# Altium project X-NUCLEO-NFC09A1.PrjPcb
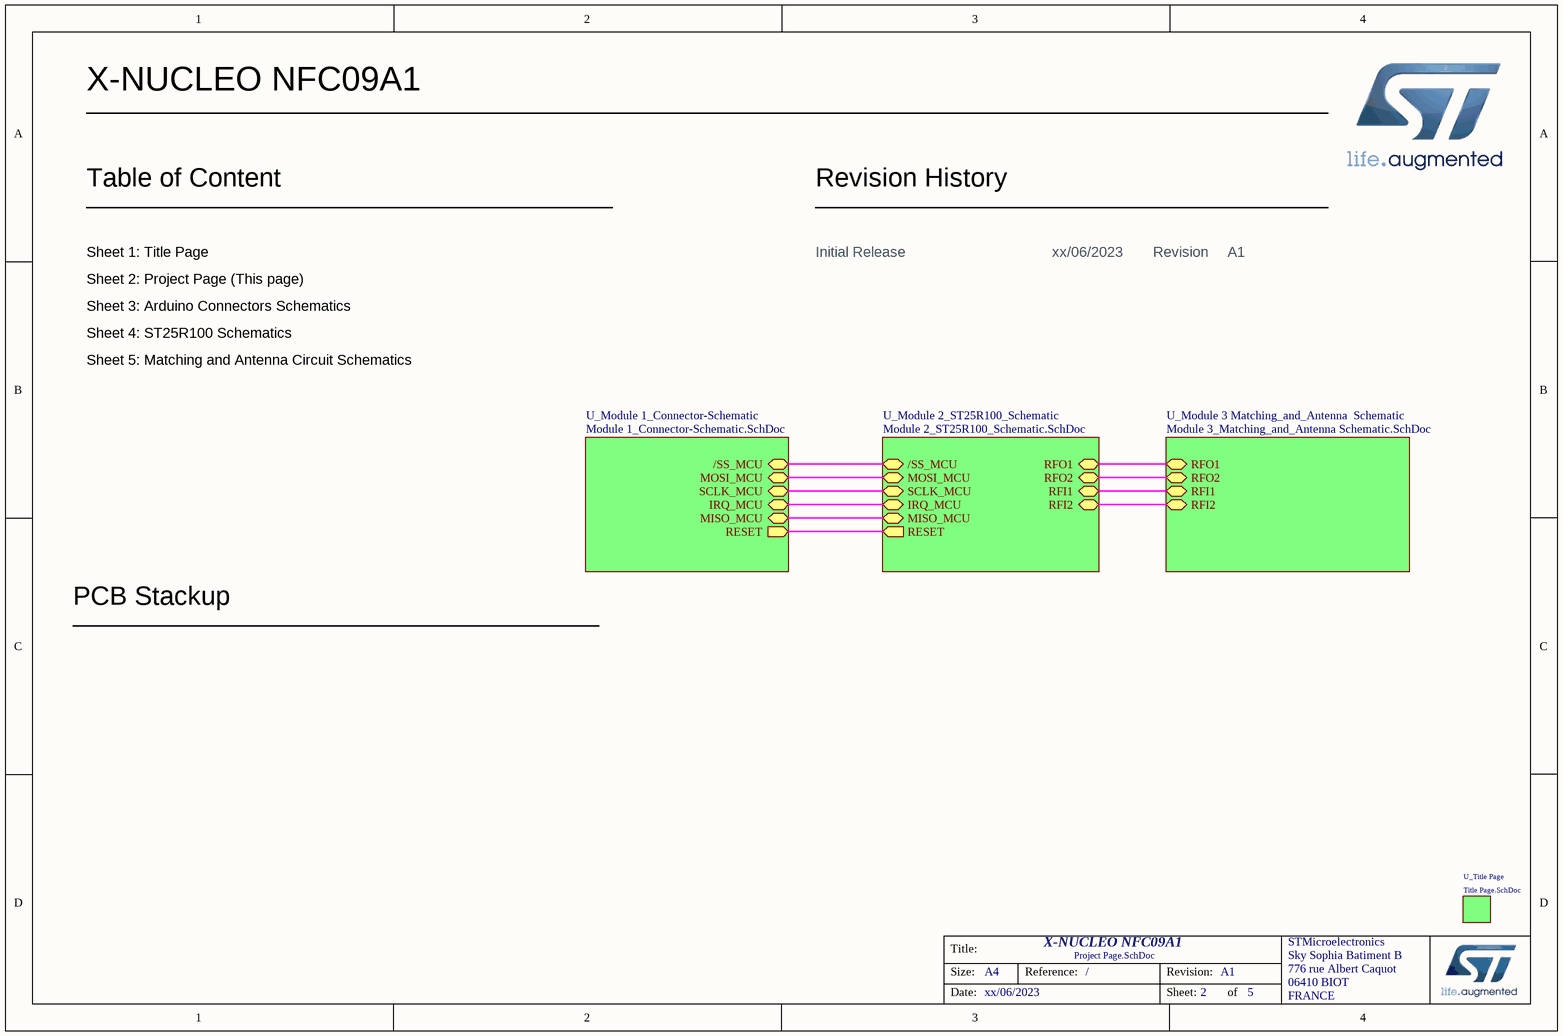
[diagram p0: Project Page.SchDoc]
Company: ST MICROELECTRONICS; date_Dossier: xx/06/2023; Reference: /; Revision: A1; Schematics_Reference: /; Schematics_Revision: A1; Schematics_Title: X-NUCLEO NFC09A1; text_ident_couches: X-NUCLEO NFC09A1; Title: X-NUCLEO NFC09A1; Titre_BOM: X-NUCLEO NFC09A1
5 sheets, 123 parts. Net scope: hierarchical (ports join the sheet entries above them; power ports are global).
Board file: X-NUCLEO-NFC09A1.PcbDoc
Sheets:
  Project Page.SchDoc
    U_Module 1_Connector-Schematic = Module 1_Connector-Schematic.SchDoc
    U_Module 3 Matching_and_Antenna  Schematic = Module 3_Matching_and_Antenna Schematic.SchDoc
    U_Module 2_ST25R100_Schematic = Module 2_ST25R100_Schematic.SchDoc
    U_Title Page = Title Page.SchDoc

## Sheet Project Page.SchDoc: X-NUCLEO NFC09A1
size A4; PageSetup: Record=PageOptions¦CenterHorizontal=True¦CenterVertical=True¦PrintScale=1.00¦XCorrection=1.00¦YCorrection=1.00¦PrintKind=0¦BorderSize=5000000¦LeftOffset=0¦BottomOffset=0¦Orientation=2¦PaperLength=1000¦PaperWidth=1000¦Scale=100¦PaperSource=7¦PrintQuality=-4¦MediaType=1¦DitherType=10¦PrintScaleMode=1¦PaperKind=A4; Revision: A1; SheetNumber: 2; SheetTotal: 5; Reference: /

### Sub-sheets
U_Module 1_Connector-Schematic = Module 1_Connector-Schematic.SchDoc: /SS_MCU (bidir), MOSI_MCU (bidir), SCLK_MCU (bidir), IRQ_MCU (bidir), MISO_MCU (bidir), RESET (out)
U_Module 2_ST25R100_Schematic = Module 2_ST25R100_Schematic.SchDoc: RFO1 (bidir), RFO2 (bidir), RFI1 (bidir), RFI2 (bidir), /SS_MCU (bidir), MOSI_MCU (bidir), SCLK_MCU (bidir), IRQ_MCU (bidir), MISO_MCU (bidir), RESET (out)
U_Module 3 Matching_and_Antenna  Schematic = Module 3_Matching_and_Antenna Schematic.SchDoc: RFO1 (bidir), RFO2 (bidir), RFI1 (bidir), RFI2 (bidir)
U_Title Page = Title Page.SchDoc: no entries

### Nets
/SS_MCU: sheet U_Module 1_Connector-Schematic//SS_MCU, sheet U_Module 2_ST25R100_Schematic//SS_MCU
IRQ_MCU: sheet U_Module 1_Connector-Schematic/IRQ_MCU, sheet U_Module 2_ST25R100_Schematic/IRQ_MCU
MISO_MCU: sheet U_Module 1_Connector-Schematic/MISO_MCU, sheet U_Module 2_ST25R100_Schematic/MISO_MCU
MOSI_MCU: sheet U_Module 1_Connector-Schematic/MOSI_MCU, sheet U_Module 2_ST25R100_Schematic/MOSI_MCU
RESET: sheet U_Module 1_Connector-Schematic/RESET, sheet U_Module 2_ST25R100_Schematic/RESET
RFI1: sheet U_Module 3 Matching_and_Antenna  Schematic/RFI1, sheet U_Module 2_ST25R100_Schematic/RFI1
RFI2: sheet U_Module 3 Matching_and_Antenna  Schematic/RFI2, sheet U_Module 2_ST25R100_Schematic/RFI2
RFO1: sheet U_Module 3 Matching_and_Antenna  Schematic/RFO1, sheet U_Module 2_ST25R100_Schematic/RFO1
RFO2: sheet U_Module 3 Matching_and_Antenna  Schematic/RFO2, sheet U_Module 2_ST25R100_Schematic/RFO2
SCLK_MCU: sheet U_Module 1_Connector-Schematic/SCLK_MCU, sheet U_Module 2_ST25R100_Schematic/SCLK_MCU

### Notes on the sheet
- Table of Content
- Revision History
- Sheet 1: Title Page
- Sheet 2: Project Page (This page)
- Sheet 3: Arduino Connectors Schematics
- Initial Release
- Revision
- A1
- Sheet 4: ST25R100 Schematics
- Sheet 5: Matching and Antenna Circuit Schematics
- PCB Stackup

## Sheet Module 1_Connector-Schematic.SchDoc: X-NUCLEO NFC09A1
size A4; PageSetup: Record=PageOptions¦CenterHorizontal=True¦CenterVertical=True¦PrintScale=0.73¦XCorrection=1.00¦YCorrection=1.00¦PrintKind=0¦BorderSize=5000000¦LeftOffset=0¦BottomOffset=0¦Orientation=2¦PaperLength=1000¦PaperWidth=1000¦Scale=100¦PaperSource=7¦PrintQuality=-3¦MediaType=1¦DitherType=10¦PrintScaleMode=1¦PaperKind=A4¦PaperIndex=9; Revision: A1; SheetNumber: 3; SheetTotal: 5; Reference: /
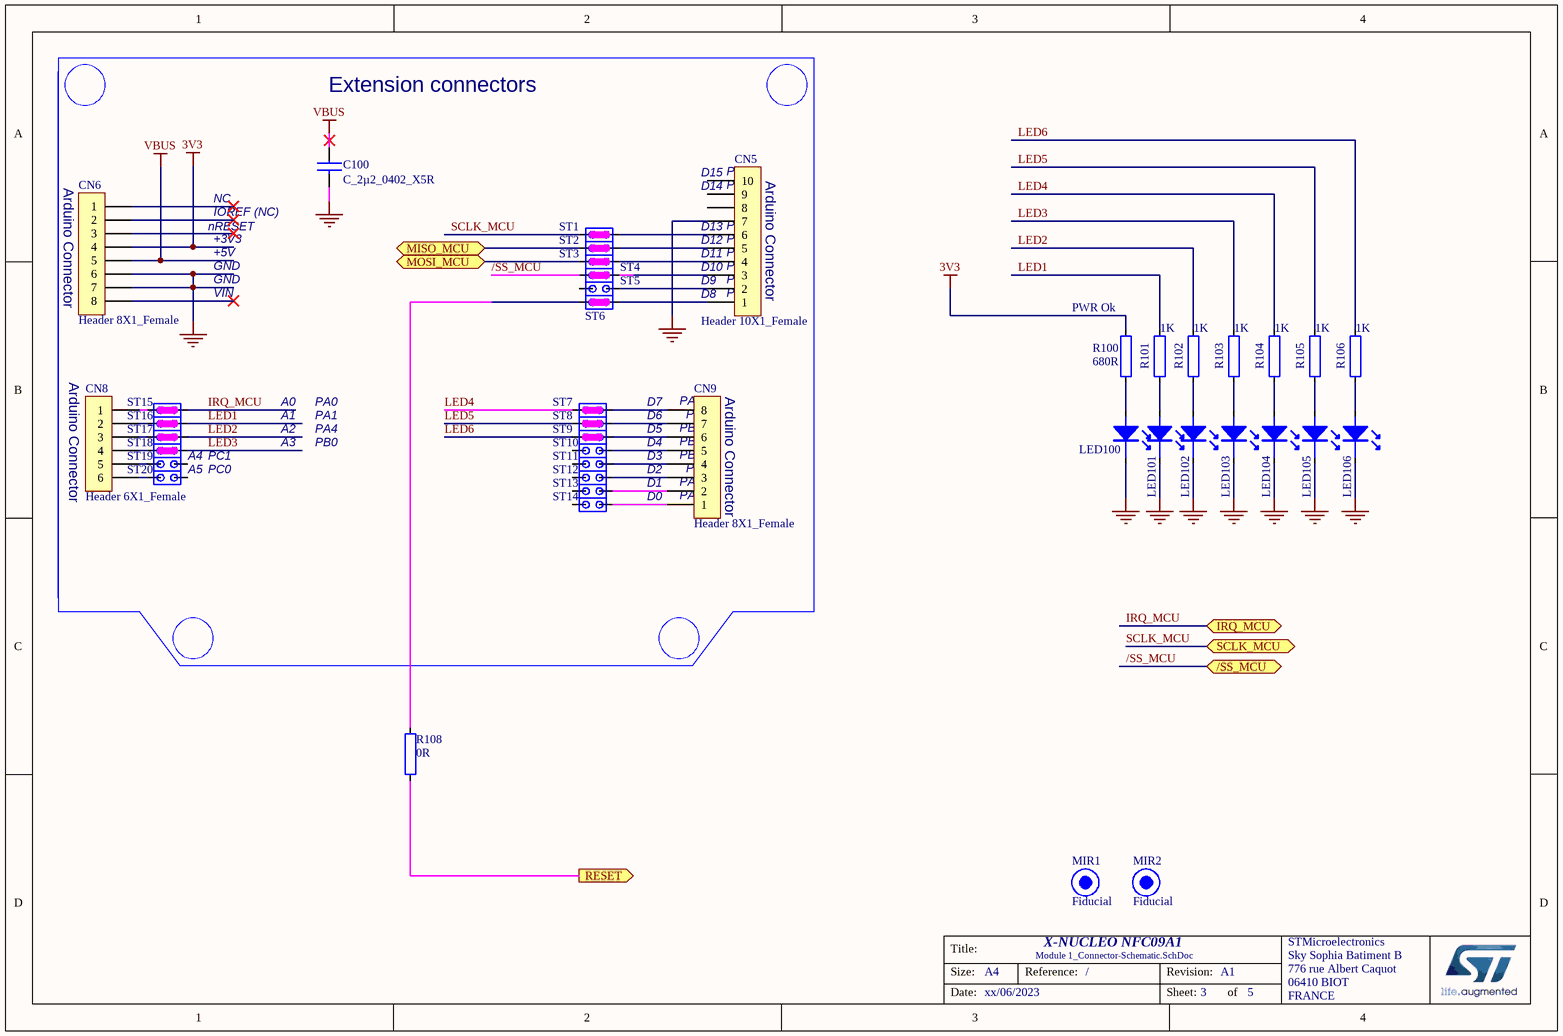
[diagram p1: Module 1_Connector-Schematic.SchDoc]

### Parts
C100  C_2µ2_0402_X5R  [C0402]
CN5  Header 10X1_Female  [SAMTEC-SSQ-1x10-DROIT-STYLE-03]
CN6  Header 8X1_Female  [SAMTEC-SSQ-1x8-DROIT-STYLE-03]
CN8  Header 6X1_Female  [SAMTEC-SSQ-1x6-DROIT-STYLE-03]
CN9  Header 8X1_Female  [SAMTEC-SSQ-1x8-DROIT-STYLE-03]
LED100  Green  [D0603]  (value not drawn)
LED101  Blue  [D0603]  (value not drawn)
LED102  Blue  [D0603]  (value not drawn)
LED103  Blue  [D0603]  (value not drawn)
LED104  Blue  [D0603]  (value not drawn)
LED105  Blue  [D0603]  (value not drawn)
LED106  Blue  [D0603]  (value not drawn)
MIR1  Fiducial  [mire_optique_standard]  (no BOM)
MIR2  Fiducial  [mire_optique_standard]  (no BOM)
R100  680R  [R0402]
R101  1K  [R0402]
R102  1K  [R0402]
R103  1K  [R0402]
R104  1K  [R0402]
R105  1K  [R0402]
R106  1K  [R0402]
R108  0R  [R0402]
ST1  HE14 2PTS NC  [HE14-1x2-DROIT-AVEC-STRAP-CUIVRE-BOTTOM]  (value not drawn)  (net tie)
ST2  HE14 2PTS NC  [HE14-1x2-DROIT-AVEC-STRAP-CUIVRE-BOTTOM]  (value not drawn)  (net tie)
ST3  HE14 2PTS NC  [HE14-1x2-DROIT-AVEC-STRAP-CUIVRE-BOTTOM]  (value not drawn)  (net tie)
ST4  HE14 2PTS NC  [HE14-1x2-DROIT-AVEC-STRAP-CUIVRE-BOTTOM]  (value not drawn)  (net tie)
ST5  HE14 2PTS NC  [HE14-1x2-DROIT]  (value not drawn)
ST6  HE14 2PTS NC  [HE14-1x2-DROIT-AVEC-STRAP-CUIVRE-BOTTOM]  (value not drawn)  (net tie)
ST7  HE14 2PTS NC  [HE14-1x2-DROIT-AVEC-STRAP-CUIVRE-BOTTOM]  (value not drawn)  (net tie)
ST8  HE14 2PTS NC  [HE14-1x2-DROIT-AVEC-STRAP-CUIVRE-BOTTOM]  (value not drawn)  (net tie)
ST9  HE14 2PTS NC  [HE14-1x2-DROIT-AVEC-STRAP-CUIVRE-BOTTOM]  (value not drawn)  (net tie)
ST10  HE14 2PTS NC  [HE14-1x2-DROIT]  (value not drawn)
ST11  HE14 2PTS NC  [HE14-1x2-DROIT]  (value not drawn)
ST12  HE14 2PTS NC  [HE14-1x2-DROIT]  (value not drawn)
ST13  HE14 2PTS NC  [HE14-1x2-DROIT]  (value not drawn)
ST14  HE14 2PTS NC  [HE14-1x2-DROIT]  (value not drawn)
ST15  HE14 2PTS NC  [HE14-1x2-DROIT-AVEC-STRAP-CUIVRE-BOTTOM]  (value not drawn)  (net tie)
ST16  HE14 2PTS NC  [HE14-1x2-DROIT-AVEC-STRAP-CUIVRE-BOTTOM]  (value not drawn)  (net tie)
ST17  HE14 2PTS NC  [HE14-1x2-DROIT-AVEC-STRAP-CUIVRE-BOTTOM]  (value not drawn)  (net tie)
ST18  HE14 2PTS NC  [HE14-1x2-DROIT-AVEC-STRAP-CUIVRE-BOTTOM]  (value not drawn)  (net tie)
ST19  HE14 2PTS NC  [HE14-1x2-DROIT-SANS-3D]  (value not drawn)
ST20  HE14 2PTS NC  [HE14-1x2-DROIT-SANS-3D]  (value not drawn)

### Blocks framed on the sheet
Extension connectors: C100 CN5 CN6 CN8 CN9 ST1-ST20

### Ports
/SS_MCU (bidir), IRQ_MCU (bidir), MISO_MCU (bidir), MOSI_MCU (bidir), RESET (out), SCLK_MCU (bidir)

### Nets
3V3: CN6.4 R100.2
GND: C100.2 CN5.7 CN6.6 CN6.7 LED100.2 LED101.2 LED102.2 LED103.2 LED104.2 LED105.2 LED106.2
VBUS: C100.1 CN6.5  [project net V_RF]
/SS_MCU: ST4.1 ; port /SS_MCU
IRQ_MCU: ST15.2 ; port IRQ_MCU
LED1: R101.2 ST16.2
LED2: R102.2 ST17.2
LED3: R103.2 ST18.2
LED4: R104.2 ST7.1
LED5: R105.2 ST8.1
LED6: R106.2 ST9.1
MISO_MCU: ST2.1 ; port MISO_MCU
MOSI_MCU: ST3.1 ; port MOSI_MCU
RESET: R108.1 ; port RESET
SCLK_MCU: ST1.1 ; port SCLK_MCU
NetCN5_1: CN5.1 ST6.2
NetCN5_2: CN5.2 ST5.2
NetCN5_3: CN5.3 ST4.2
NetCN5_4: CN5.4 ST3.2
NetCN5_5: CN5.5 ST2.2
NetCN5_6: CN5.6 ST1.2
NetCN8_1: CN8.1 ST15.1
NetCN8_2: CN8.2 ST16.1
NetCN8_3: CN8.3 ST17.1
NetCN8_4: CN8.4 ST18.1
NetCN8_5: CN8.5 ST19.1
NetCN8_6: CN8.6 ST20.1
NetCN9_1: CN9.1 ST14.2
NetCN9_2: CN9.2 ST13.2
NetCN9_3: CN9.3 ST12.2
NetCN9_4: CN9.4 ST11.2
NetCN9_5: CN9.5 ST10.2
NetCN9_6: CN9.6 ST9.2
NetCN9_7: CN9.7 ST8.2
NetCN9_8: CN9.8 ST7.2
NetLED100_1: LED100.1 R100.1
NetLED101_1: LED101.1 R101.1
NetLED102_1: LED102.1 R102.1
NetLED103_1: LED103.1 R103.1
NetLED104_1: LED104.1 R104.1
NetLED105_1: LED105.1 R105.1
NetLED106_1: LED106.1 R106.1
NetR108_2: R108.2 ST6.1

Not connected (* = marked no-connect by the designer): CN5 8 9 10; CN6 1* 2* 3* 8*; ST5 1; ST10 1; ST11 1; ST12 1; ST13 1; ST14 1; ST19 2; ST20 2

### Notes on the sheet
- (near CN5) D15
- (near CN5) PB8
- (near CN5) Arduino Connector
- (near CN6) Arduino Connector
- nRESET
- NC
- IOREF (NC)
- +3V3
- (near CN5) D14
- (near CN5) D13
- (near CN5) D12
- (near CN5) PB9
- (near CN5) PA5
- (near CN5) PA6
- +5V
- GND
- VIN
- (near CN5) D8
- (near CN5) D9
- (near CN5) D10
- (near CN5) D11
- (near CN5) PA7
- (near CN5) PB6
- (near CN5) PC7
- (near CN5) PA9
- (near R100) PWR Ok
- (near CN8) Arduino Connector
- A0
- A1
- A2
- A3
- PA0
- PA1
- PA4
- PB0
- D4
- D5
- D6
- D7
- (near CN9) PA8
- (near CN9) PB4
- (near CN9) PB5
- (near CN9) PB10
- (near CN9) Arduino Connector
- A4
- A5
- PC1
- PC0
- D0
- D1
- D2
- D3
- (near CN9) PB3
- (near CN9) PA2
- (near CN9) PA3
- (near CN9) PA10

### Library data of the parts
C100 = C_2µ2_0402_X5R: 2u2_X5R; Manufacturer: MURATA; Manufacturer Part Number: GRM155R60J225ME15D; 2nd Source: 0402, 2.2 µF, 6.3 V, ± 20%, X5R; PickPlace: Yes
CN5 = Header 10X1_Female: Header, 10-Pin, Single row,female; Manufacturer: Samtec; Manufacturer Part Number: SSQ-110-03-L-S; Comments: RECEPTACLE, 2.54MM, SINGLE ROW, 10WAY; 2nd source: doublesourcing allowed; PickPlace: No
CN6 CN9 = Header 8X1_Female: Header, 8-Pin, Single row,female; Manufacturer: Samtec; Manufacturer Part Number: SSQ-108-03-L-S; Comments: RECEPTACLE, 2.54MM, SINGLE ROW, 8WAY; 2nd source: doublesourcing allowed; PickPlace: No
CN8 = Header 6X1_Female: Header, 6-Pin, Single row,female; Manufacturer: Samtec; Manufacturer Part Number: SSQ-106-03-L-S; Comments: RECEPTACLE, 2.54MM, SINGLE ROW, 6 WAY; 2nd source: doublesourcing allowed; PickPlace: No
LED100 = LED-0603-Green: Manufacturer: Lite-On; Manufacturer Part Number: LTST-C190KGKT; PickPlace: Yes
LED101-LED106 = LED-0603-Blue: Manufacturer: Lite-On; Manufacturer Part Number: LTST-C190TBKT; PickPlace: Yes
MIR1 MIR2 = Mire-Optique: Fiducial for SMD Components; PickPlace: Yes
R100 = R0402_680R: 680R, 0402; Manufacturer: Yageo; Manufacturer Part Number: RC0402JR-07680RL; 2nd Source: 680 Ohm ±5% 0.063W, 1/16W Chip Resistor 0402; PickPlace: Yes
R101-R106 = R0402_1k: 1k, 0402; Manufacturer: Panasonic; Manufacturer Part Number: ERJ2GEJ102X; 2nd Source: 1 kohm, 50 V, 0402, >100 mW, ± 5%; PickPlace: Yes
R108 = R0402_0R: 0R, 0402; Manufacturer: MULTI-SOURCES; Manufacturer Part Number: RESISTOR 0402 0R 62mW; 2nd Source: 0 ohm, 50 V, 0402, >62.5 mW; PickPlace: Yes
ST1-ST4 ST7-ST9 ST15-ST18 = HE14-1X2-MALE-DROIT-NC-STRAP-CUIVRE-BOTTOM: CONN HE14 2PTS MALE VERTICAL NOT FITTED; 2nd Source: doublesourcing allowed; PickPlace: No
ST5 ST10-ST14 = HE14-1X2-MALE-DROIT-NC: CONN HE14 2PTS MALE VERTICAL NOT FITTED; 2nd Source: doublesourcing allowed; PickPlace: No
ST6 = HE14-1X2-MALE-DROIT-NC-STRAP-CUIVRE-BOTTOM: CONN HE14 2PTS MALE VERTICAL NOT FITTED; Manufacturer: MULTI SOURCES; 2nd Source: doublesourcing allowed; PickPlace: No
ST19 ST20 = HE14-1X2-MALE-DROIT-NC: CONN HE14 2PTS MALE VERTICAL NOT FITTED; Manufacturer: MULTI-SOURCES; 2nd Source: doublesourcing allowed; PickPlace: No

## Sheet Module 3_Matching_and_Antenna Schematic.SchDoc: X-NUCLEO NFC09A1
size A4; PageSetup: Record=PageOptions¦CenterHorizontal=True¦CenterVertical=True¦PrintScale=0.97¦XCorrection=1.00¦YCorrection=1.00¦PrintKind=0¦BorderSize=5000000¦LeftOffset=0¦BottomOffset=0¦Orientation=2¦PaperLength=1000¦PaperWidth=1000¦Scale=100¦PaperSource=7¦PrintQuality=-4¦MediaType=1¦DitherType=10¦PaperKind=A4¦PrintScaleMode=1; Revision: A1; SheetNumber: 5; SheetTotal: 5; Reference: /
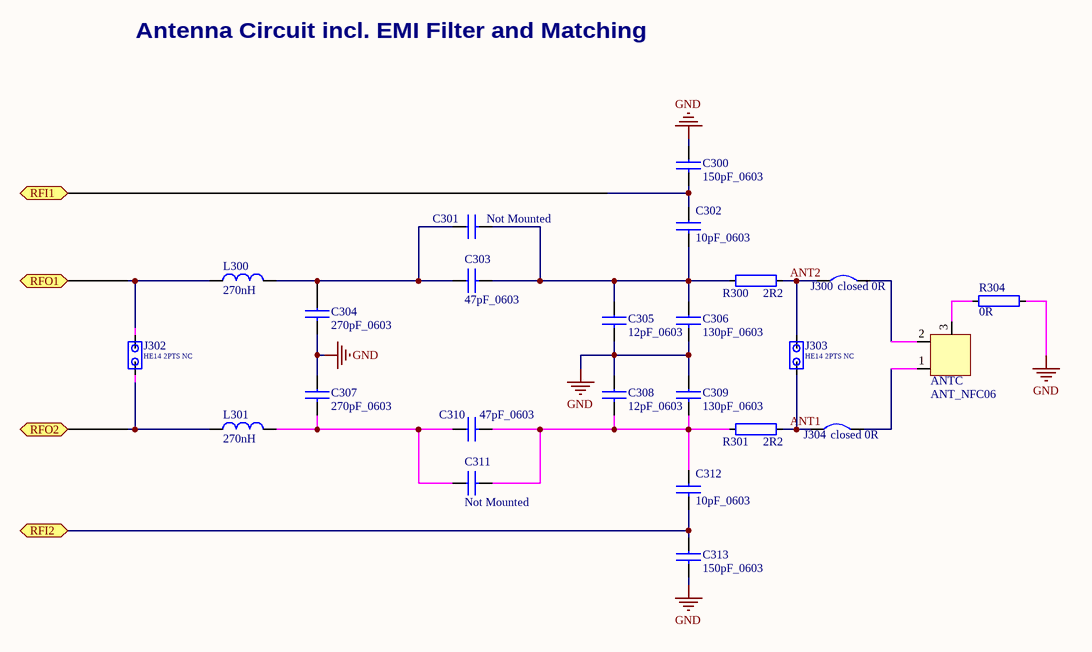
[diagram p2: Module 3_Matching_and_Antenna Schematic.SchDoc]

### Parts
ANTC  ANT_NFC06  [ANT_NFC08]  (net tie, no BOM)
C300  150pF_0603  [C0603]
C301  Not Mounted  [C0603]
C302  10pF_0603  [C0603]
C303  47pF_0603  [C0603]
C304  270pF_0603  [C0603]
C305  12pF_0603  [C0603]
C306  130pF_0603  [C0603]
C307  270pF_0603  [C0603]
C308  12pF_0603  [C0603]
C309  130pF_0603  [C0603]
C310  47pF_0603  [C0603]
C311  Not Mounted  [C0603]
C312  10pF_0603  [C0603]
C313  150pF_0603  [C0603]
J300  closed 0R  [JP2_SMD_closed_0402]  (net tie)
J302  HE14 2PTS NC  [HE14-1x2-DROIT-sans-3D-largeur-1.8]
J303  HE14 2PTS NC  [HE14-1x2-DROIT-sans-3D-largeur-1.8]
J304  closed 0R  [JP2_SMD_closed_0402]  (net tie)
L300  270nH  [L0603]
L301  270nH  [L0603]
R300  2R2  [R0603]
R301  2R2  [R0603]
R304  0R  [R0603]

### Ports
RFI1 (bidir), RFI2 (bidir), RFO1 (bidir), RFO2 (bidir)

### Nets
GND: C300.1 C304.2 C305.2 C306.2 C307.1 C308.1 C309.1 C313.2 R304.1
ANT1: J303.2 J304.1 R301.1
ANT2: J300.1 J303.1 R300.1
RFI1: C300.2 C302.1 ; port RFI1
RFI2: C312.2 C313.1 ; port RFI2
RFO1: J302.1 L300.2 ; port RFO1
RFO2: J302.2 L301.2 ; port RFO2
NetANTC_1: ANTC.1 J304.2
NetANTC_2: ANTC.2 J300.2
NetANTC_3: ANTC.3 R304.2
NetC301_1: C301.1 C303.1 C304.1 L300.1
NetC301_2: C301.2 C302.2 C303.2 C305.1 C306.1 R300.2
NetC307_2: C307.2 C310.1 C311.1 L301.1
NetC308_2: C308.2 C309.2 C310.2 C311.2 C312.1 R301.2

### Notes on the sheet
- Antenna Circuit incl. EMI Filter and Matching

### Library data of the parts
ANTC = ANT_NFC06: PickPlace: No
C300 C313 = C_150p_0603: 150p_COG 0603; Manufacturer: MURATA; Manufacturer Part Number: GRM1885C1H151GA01D; PickPlace: Yes
C301 C311 = C_12p_0603: Manufacturer: MULTI-SOURCES; PickPlace: Yes
C302 C312 = C_10p_0603: 10p_COG; Manufacturer: MULTICOMP; Manufacturer Part Number: MC0603N100F500CT; PickPlace: Yes
C303 = C_82p_0603: 47p_COG; Manufacturer: MURATA; Manufacturer Part Number: GCM1555C1H47FA16D; 2nd Source: 82pF ±1% 50V  C0G, NP0 0603; PickPlace: Yes
C304 C307 = C_680p_0603: 270p_COG; Manufacturer: MURATA; Manufacturer Part Number: GCM1555C1H271FA01D; 2nd Source: 270pF ±2% 50V  C0G, NP0 0603; PickPlace: Yes
C305 C308 = C_5p6_0603: 12pF_COG 0603; Manufacturer: MURATA; Manufacturer Part Number: GRM1555C1H120GA01D; PickPlace: Yes
C306 C309 = C_120p_0603: 130pF_COG; Manufacturer: MURATA; Manufacturer Part Number: GCM1555C1H131FA16D; 2nd Source: 130pF ±1% 50V  C0G, NP0 0603; PickPlace: Yes
C310 = C_82p_0603: 47p_COG; Manufacturer: MURATA; Manufacturer Part Number: GCM1555C1H47FA16D; 2nd Source: 47pF ±1% 50V  C0G, NP0 0603; PickPlace: Yes
J300 J304 = solder_jumper_closed_0402: 0R 0402; Manufacturer: MULTI-SOURCES; Manufacturer Part Number: RESISTOR 0402 0R 62mW; PickPlace: Yes
J302 J303 = HE14-1X2-MALE-DROIT-NC-special: CONN HE14 2PTS MALE VERTICAL NOT FITTED; Manufacturer: MULTI-SOURCES; 2nd Source: doublesourcing allowed; PickPlace: No
L300 L301 = 0603LS-271XGLB: 0603LS-271XGRC; Manufacturer: COILCRAFT; PickPlace: Yes
R300 R301 = R0603_2R2: 2R2, 0603; Manufacturer: MULTI-SOURCES; Manufacturer Part Number: RESISTOR 0603 2.2 Ohms 1%; PickPlace: Yes
R304 = R0603_0R: 0R, 0603; Manufacturer: MULTI-SOURCES; Manufacturer Part Number: RESISTOR 0603 0R 62mW; PickPlace: Yes

## Sheet Module 2_ST25R100_Schematic.SchDoc: X-NUCLEO NFC09A1
size A4; PageSetup: Record=PageOptions¦CenterHorizontal=True¦CenterVertical=True¦PrintScale=0.97¦XCorrection=1.00¦YCorrection=1.00¦PrintKind=0¦BorderSize=5000000¦LeftOffset=0¦BottomOffset=0¦Orientation=2¦PaperLength=1000¦PaperWidth=1000¦Scale=100¦PaperSource=7¦PrintQuality=-4¦MediaType=1¦DitherType=10¦PaperKind=A4¦PrintScaleMode=1; Revision: A1; SheetNumber: 4; SheetTotal: 5; Reference: /
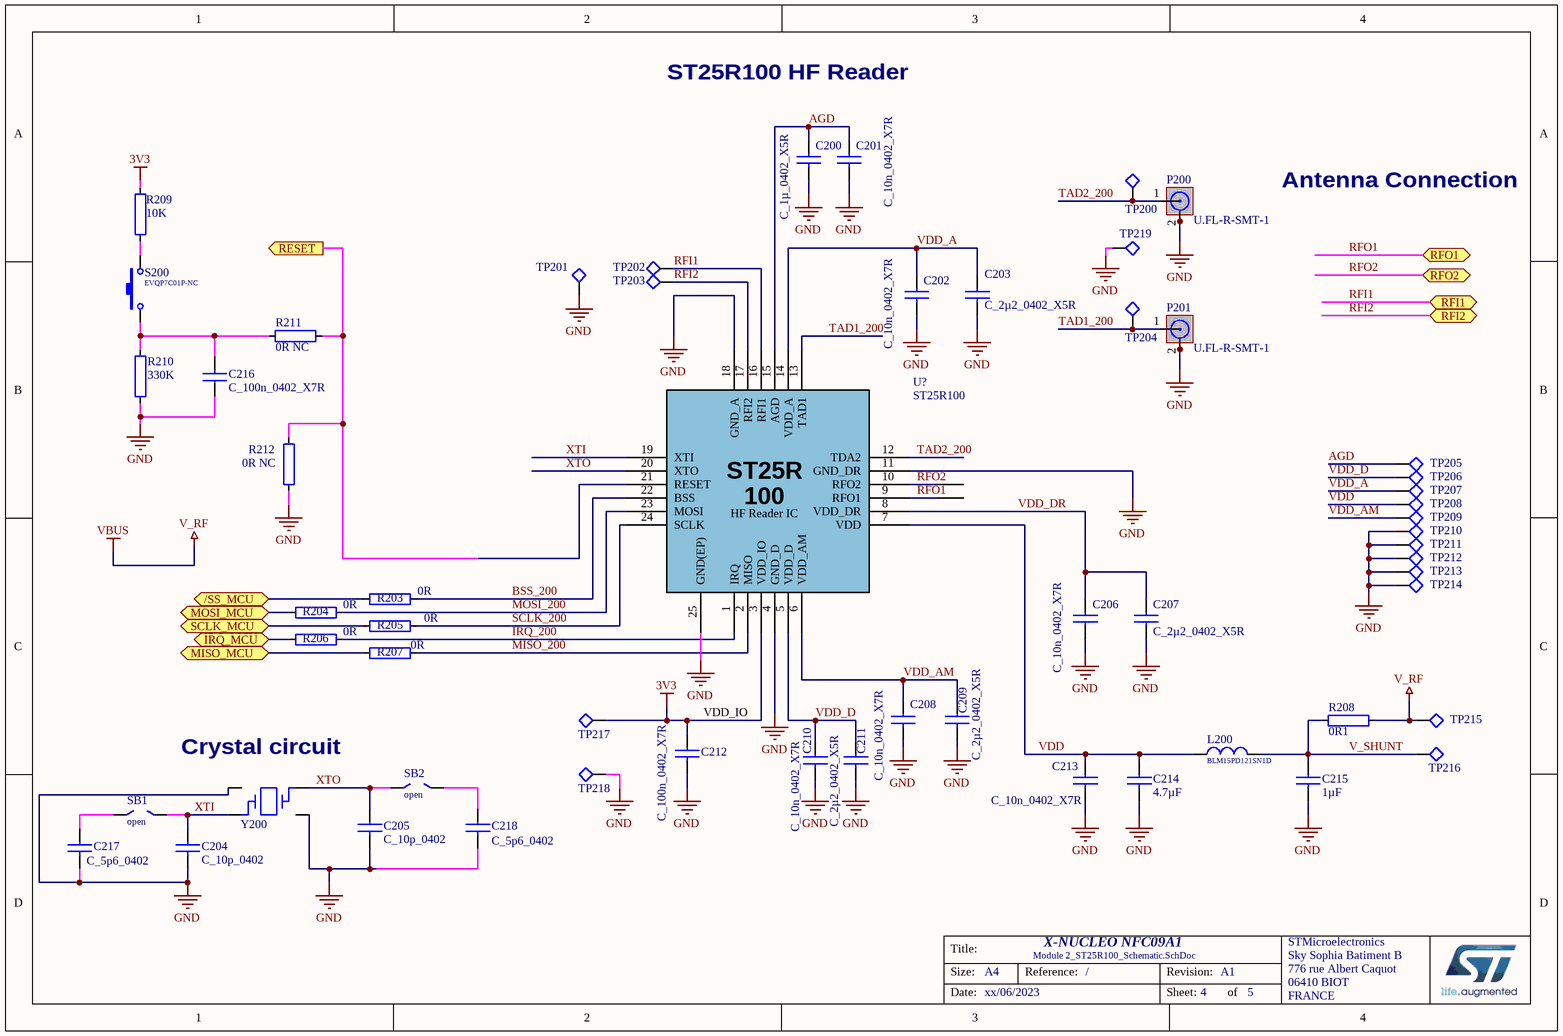
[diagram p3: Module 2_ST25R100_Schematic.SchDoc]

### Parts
C200  C_1µ_0402_X5R  [C0402]
C201  C_10n_0402_X7R  [C0402]
C202  C_10n_0402_X7R  [C0402]
C203  C_2µ2_0402_X5R  [C0402]
C204  C_10p_0402  [C0402]
C205  C_10p_0402  [C0402]
C206  C_10n_0402_X7R  [C0402]
C207  C_2µ2_0402_X5R  [C0402]
C208  C_10n_0402_X7R  [C0402]
C209  C_2µ2_0402_X5R  [C0402]
C210  C_10n_0402_X7R  [C0402]
C211  C_2µ2_0402_X5R  [C0402]
C212  C_100n_0402_X7R  [C0402]
C213  C_10n_0402_X7R  [C0402]
C214  4.7µF  [C0402]
C215  1µF  [C0402]
C216  C_100n_0402_X7R  [C0402]
C217  C_5p6_0402  [C0402]
C218  C_5p6_0402  [C0402]
L200  BLM15PD121SN1D  [L0402]
P200  U.FL-R-SMT-1  [U FL Socket - HRS - Surface Mount]
P201  U.FL-R-SMT-1  [U FL Socket - HRS - Surface Mount]
R203  0R  [R0402]
R204  0R  [R0402]
R205  0R  [R0402]
R206  0R  [R0402]
R207  0R  [R0402]
R208  0R1  [R0603]
R209  10K  [R0402]
R210  330K  [R0402]
R211  0R NC  [R0402]
R212  0R NC  [R0402]
S200  EVQP7C01P-NC  [PANASONIC-SWITCH-EVQP7C/EVQP7L]
SB1  open  [solder-bridge-0402]  (no BOM)
SB2  open  [solder-bridge-0402]  (no BOM)
TP200  (no value)  [1*1P_MALE]  (no BOM)
TP201  Test point percage 1mm-pad-carree  [1*1P_MALE]  (value not drawn)  (no BOM)
TP202  Test point percage 1mm-pad-carree  [1*1P_MALE]  (value not drawn)  (no BOM)
TP203  Test point percage 1mm-pad-carree  [1*1P_MALE]  (value not drawn)  (no BOM)
TP204  (no value)  [1*1P_MALE]  (no BOM)
TP205  Test point percage 1mm  [1*1P_MALE round]  (value not drawn)  (no BOM)
TP206  Test point percage 1mm  [1*1P_MALE round]  (value not drawn)  (no BOM)
TP207  Test point percage 1mm  [1*1P_MALE round]  (value not drawn)  (no BOM)
TP208  Test point percage 1mm  [1*1P_MALE round]  (value not drawn)  (no BOM)
TP209  Test point percage 1mm  [1*1P_MALE round]  (value not drawn)  (no BOM)
TP210  Test point percage 1mm  [1*1P_MALE round]  (value not drawn)  (no BOM)
TP211  Test point percage 1mm  [1*1P_MALE round]  (value not drawn)  (no BOM)
TP212  Test point percage 1mm  [1*1P_MALE round]  (value not drawn)  (no BOM)
TP213  Test point percage 1mm  [1*1P_MALE round]  (value not drawn)  (no BOM)
TP214  Test point percage 1mm  [1*1P_MALE round]  (value not drawn)  (no BOM)
TP215  Test point percage 1mm  [1*1P_MALE round]  (value not drawn)  (no BOM)
TP216  Test point percage 1mm  [1*1P_MALE round]  (value not drawn)  (no BOM)
TP217  Test point percage 1mm  [1*1P_MALE round]  (value not drawn)  (no BOM)
TP218  Test point percage 1mm  [1*1P_MALE round]  (value not drawn)  (no BOM)
TP219  (no value)  [1*1P_MALE]  (no BOM)
U?  ST25R100  [ST25R200 QFN]
Y200  NDK 27,12MHz Crystal  [XRCGB_F_MN]  (value not drawn)

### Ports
/SS_MCU (bidir), IRQ_MCU (bidir), MISO_MCU (bidir), MOSI_MCU (bidir), RESET (out), RFI1 (bidir), RFI2 (bidir), RFO1 (bidir), RFO2 (bidir), SCLK_MCU (bidir)

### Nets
3V3: C212.1 R209.2 TP217.1 U?.3(VDD_IO)
GND: C200.2 C201.2 C202.2 C203.2 C204.2 C205.2 C206.2 C207.2 C208.2 C209.2 C210.2 C211.2 C212.2 C213.2 C214.2 C215.2 C216.1 C217.2 C218.2 P200.2 P200.3 P201.2 P201.3 R210.1 R212.2 TP201.1 TP210.1 TP211.1 TP212.1 TP213.1 TP214.1 TP218.1 TP219.1 U?.4(GND_D) U?.11(GND_DR) U?.18(GND_A) U?.25(GND(EP)) Y200.2 Y200.4
V_RF: R208.2 TP215.1  [also labelled VBUS]
/SS_MCU: R203.1 ; port /SS_MCU
AGD: C200.1 C201.1 TP205.1 U?.15(AGD)
BSS_200: R203.2 U?.22(BSS)
IRQ_200: R206.2 U?.1(IRQ)
IRQ_MCU: R206.1 ; port IRQ_MCU
MISO_200: R207.2 U?.2(MISO)
MISO_MCU: R207.1 ; port MISO_MCU
MOSI_200: R204.2 U?.23(MOSI)
MOSI_MCU: R204.1 ; port MOSI_MCU
RESET: R211.1 R212.1 U?.21(RESET) ; port RESET
RFI1: TP202.1 U?.16(RFI1) ; port RFI1
RFI2: TP203.1 U?.17(RFI2) ; port RFI2
RFO1: U?.9(RFO1) ; port RFO1
RFO2: U?.10(RFO2) ; port RFO2
SCLK_200: R205.2 U?.24(SCLK)
SCLK_MCU: R205.1 ; port SCLK_MCU
TAD1_200: P201.1 TP204.1 U?.13(TAD1)
TAD2_200: P200.1 TP200.1 U?.12(TDA2)
V_SHUNT: C215.1 L200.1 R208.1 TP216.1
VDD: C213.1 C214.1 L200.2 TP208.1 U?.7(VDD)
VDD_A: C202.1 C203.1 TP207.1 U?.14(VDD_A)
VDD_AM: C208.1 C209.1 TP209.1 U?.6(VDD_AM)
VDD_D: C210.1 C211.1 TP206.1 U?.5(VDD_D)
VDD_DR: C206.1 C207.1 U?.8(VDD_DR)
XTI: C204.1 SB1.2 U?.19(XTI) Y200.3
XTO: C205.1 SB2.1 U?.20(XTO) Y200.1
NetC216_2: C216.2 R210.2 R211.2 S200.1
NetC217_1: C217.1 SB1.1
NetC218_1: C218.1 SB2.2
NetR209_1: R209.1 S200.2

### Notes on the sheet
- ST25R100 HF Reader
- Antenna Connection
- (near C212) VDD_IO
- (near Y200) Crystal circuit

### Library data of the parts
C200 C215 = C_1µ_0402_X5R: 1u_X5R; Manufacturer: MURATA; Manufacturer Part Number: GRM155R61C105KA12D; 2nd Source: 0402, 1 µF, 16 V, ± 10%, X5R,; PickPlace: Yes
C201 C202 C206 C208 C210 C213 = C_10n_0402_X7R: 10n_x7R; Manufacturer: AVX; Manufacturer Part Number: 04023C103KAT2A; 2nd Source: 0402, 0.01 µF, 25 V, ± 10%, X7R; PickPlace: Yes
C203 C207 C209 C211 = C_2µ2_0402_X5R: as C100 on sheet Module 1_Connector-Schematic
C204 C205 = C_10p_0402: 10p_C0G; Manufacturer: MURATA; Manufacturer Part Number: GRM1555C1H100GA01D; 2nd Source: 0402, 0.01 µF, 25 V, ± 10%, X7R; PickPlace: Yes
C212 C216 = C_100n_0402_X7R: 100n_x7R 0402; Manufacturer: MULTICOMP; Manufacturer Part Number: MC0402X104K100CT; 2nd Source: 0402, 0.1 µF, 10 V, ± 10%, X7R; PickPlace: Yes
C214 = C_4µ7_0402_X5R_10V: 4u7_X5R_10V_0402; Manufacturer: MURATA; Manufacturer Part Number: GRM155R61A475MEAA; PickPlace: Yes
C217 C218 = C_10p_0402: 5P6_C0G; Manufacturer: MURATA; Manufacturer Part Number: GRM1555C1H5R6BA01D; PickPlace: Yes
L200 = BLM15PD121SN1D: FERRITE BEAD; Manufacturer: MURATA; PickPlace: Yes
P200 P201 = U.FL-R-SMT-1: Manufacturer: HIROSE(HRS); Manufacturer Part Number: U.FL-R-SMT-1(10); 2nd Source: yes
R203-R207 = R0402_0R: as R108 on sheet Module 1_Connector-Schematic
R208 = R0603_0R1: 0R1, 0603; Manufacturer: OHMITE; Manufacturer Part Number: KDV06DR100ET; PickPlace: Yes
R209 = R0402_10K: 10K, 0402; Manufacturer: MULTI-SOURCES; Manufacturer Part Number: 0402 10K 1%; PickPlace: Yes
R210 = R0402_330K: 330K, 0402; Manufacturer: MULTI-SOURCES; Manufacturer Part Number: 0402 330K 1%; PickPlace: Yes
R211 R212 = R0402_0R_NC: 0R, 0402 NOT FITTED; Manufacturer: MULTICOMP; Manufacturer Part Number: MC00625W040210R NOT FITTED; 2nd Source: 0 ohm, 50 V, 0402, >62.5 mW NOT FITTED; PickPlace: Yes
S200 = EVQP7C01P-NC: SIDE SWITCH NOT FITTED; Manufacturer: PANASONIC; Manufacturer Part Number: EVQP7C01P NOT FITTED; PickPlace: Yes
SB1 SB2 = solder_jumper_open_0402
TP200-TP204 TP219 = Test point percage 1mm-pad-carree: Part Number: Test point 0.5mm; PickPlace: No
TP205 TP206 TP208-TP218 = Test point percage 1mm: Part Number: Test point 0.5mm; Value: d.n.p.; PickPlace: No
TP207 = Test point percage 1mm: Part Number: Test point 0.5mm; PickPlace: No
U? = ST25R100: HF READER ST25R100 QFN24; Manufacturer: ST MICRO; Manufacturer Part Number: ST25R200; PickPlace: Yes
Y200 = NDK NX2016SA: NDK NX2016SA 27.12MHz; Manufacturer Part Number: NX2016SA STD-CZS-5 27.12MHz; 2nd Source: Murata XRCGB27M120F3M00R0; PickPlace: Yes

## Sheet Title Page.SchDoc: X-NUCLEO NFC09A1
size A4; PageSetup: Record=PageOptions¦CenterHorizontal=True¦CenterVertical=True¦PrintScale=1.00¦XCorrection=1.00¦YCorrection=1.00¦PrintKind=0¦BorderSize=5000000¦LeftOffset=0¦BottomOffset=0¦Orientation=2¦PaperLength=1000¦PaperWidth=1000¦Scale=100¦PaperSource=7¦PrintQuality=-3¦MediaType=1¦DitherType=10¦PrintScaleMode=1¦PaperKind=A4¦PaperIndex=9; Revision: A1; SheetNumber: 1; SheetTotal: 5; Reference: /
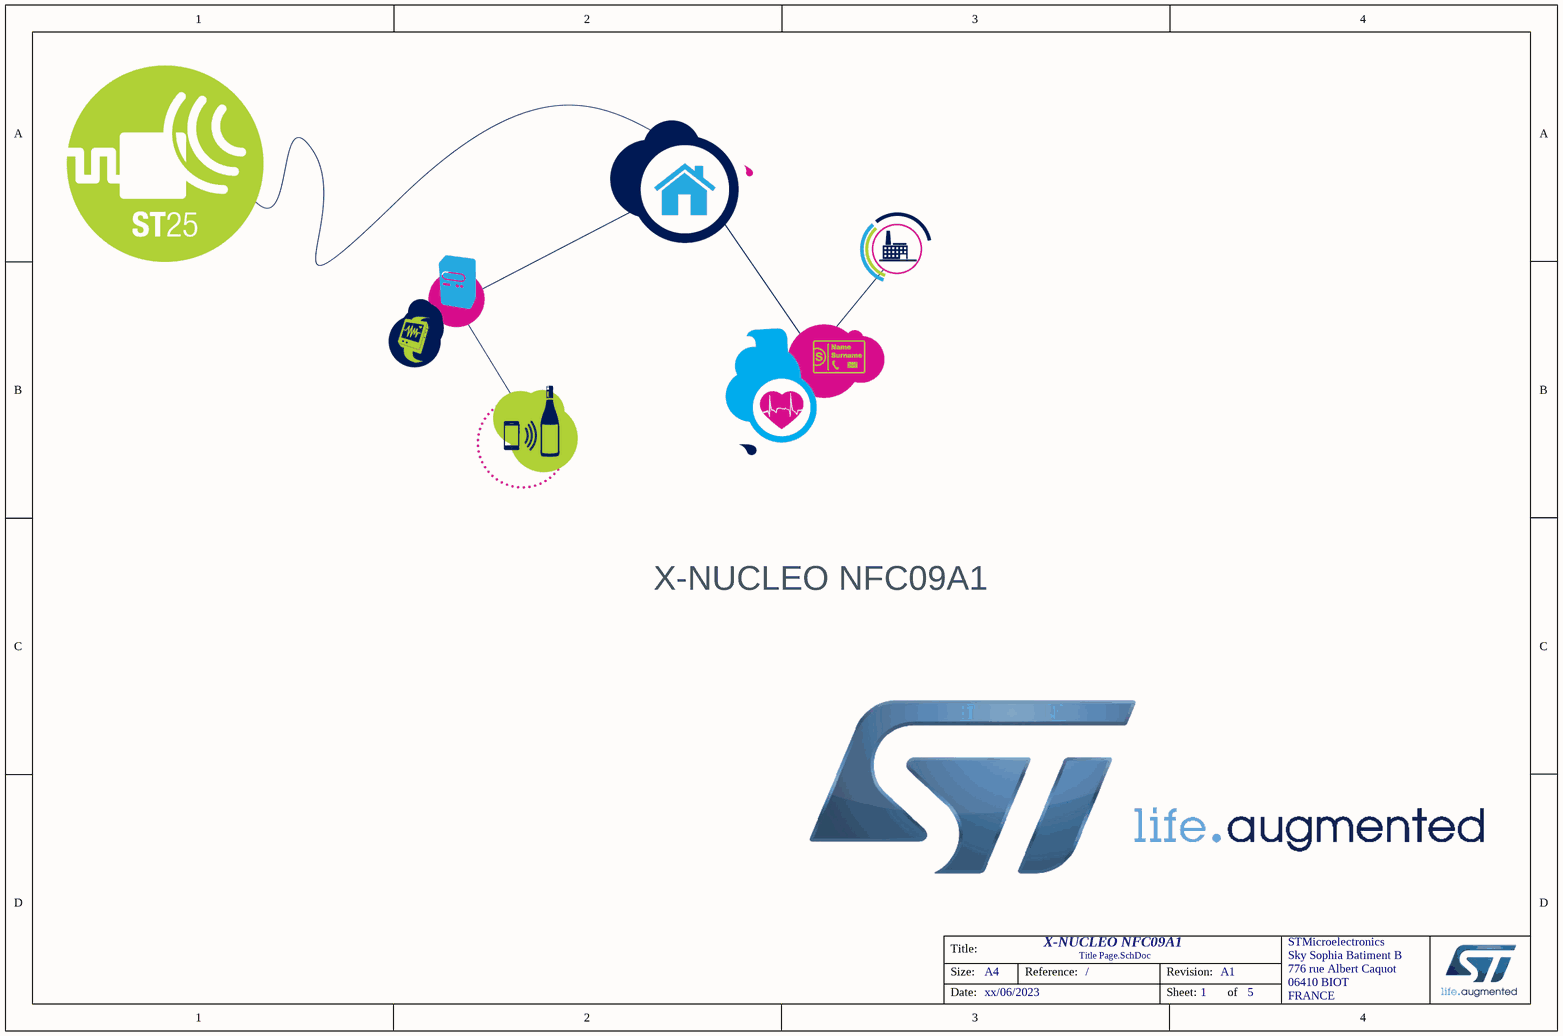
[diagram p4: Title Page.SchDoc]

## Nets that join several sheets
3V3: Module 1_Connector-Schematic (CN6.4 R100.2), Module 2_ST25R100_Schematic (C212.1 R209.2 TP217.1 U?.3)
GND: Module 1_Connector-Schematic (11 pins), Module 3_Matching_and_Antenna Schematic (9 pins), Module 2_ST25R100_Schematic (39 pins)
V_RF: Module 1_Connector-Schematic (C100.1 CN6.5), Module 2_ST25R100_Schematic (R208.2 TP215.1)
/SS_MCU: Module 1_Connector-Schematic (ST4.1), Module 2_ST25R100_Schematic (R203.1)
IRQ_MCU: Module 1_Connector-Schematic (ST15.2), Module 2_ST25R100_Schematic (R206.1)
MISO_MCU: Module 1_Connector-Schematic (ST2.1), Module 2_ST25R100_Schematic (R207.1)
MOSI_MCU: Module 1_Connector-Schematic (ST3.1), Module 2_ST25R100_Schematic (R204.1)
RESET: Module 1_Connector-Schematic (R108.1), Module 2_ST25R100_Schematic (R211.1 R212.1 U?.21)
RFI1: Module 3_Matching_and_Antenna Schematic (C300.2 C302.1), Module 2_ST25R100_Schematic (TP202.1 U?.16)
RFI2: Module 3_Matching_and_Antenna Schematic (C312.2 C313.1), Module 2_ST25R100_Schematic (TP203.1 U?.17)
RFO1: Module 3_Matching_and_Antenna Schematic (J302.1 L300.2), Module 2_ST25R100_Schematic (U?.9)
RFO2: Module 3_Matching_and_Antenna Schematic (J302.2 L301.2), Module 2_ST25R100_Schematic (U?.10)
SCLK_MCU: Module 1_Connector-Schematic (ST1.1), Module 2_ST25R100_Schematic (R205.1)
